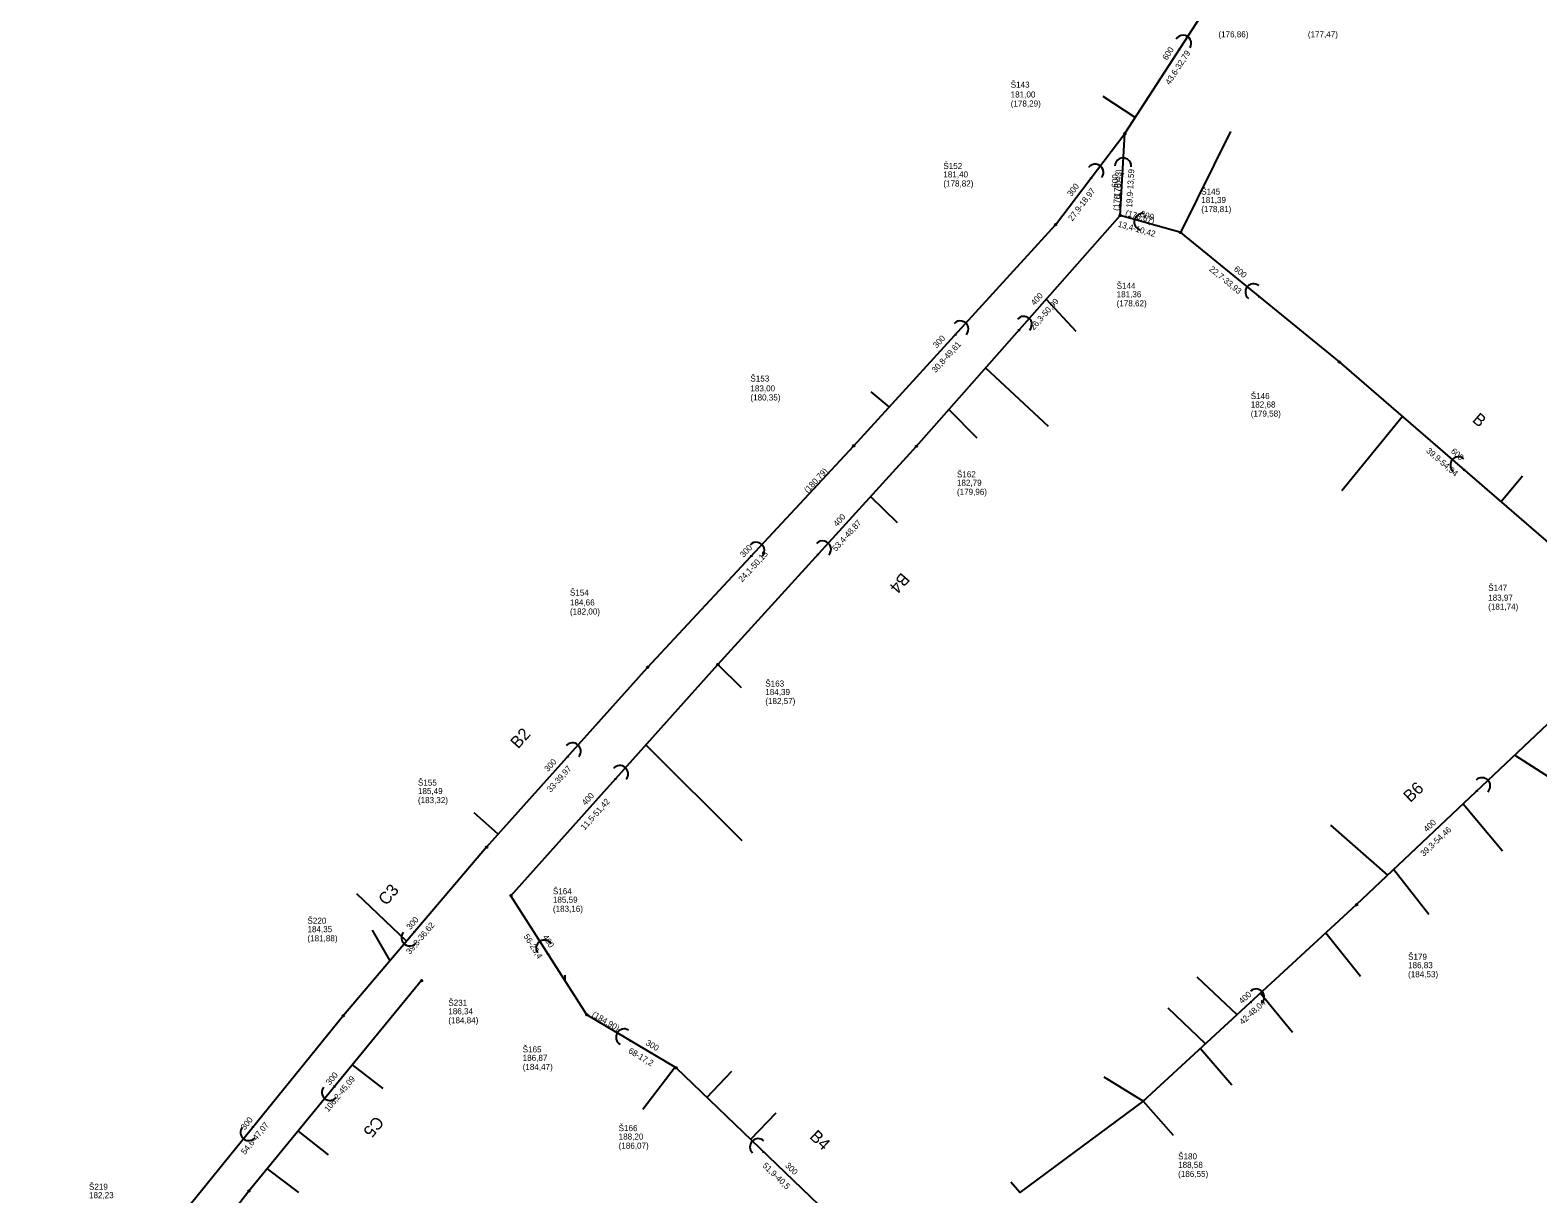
# Model space of a CAD drawing. Extents: x -548529 to -543591, y -1201432 to -1192608.
# Drawn here: x -547313.2 to -547063.4, y -1195608.4 to -1195415.6 of the extents above; entities that cross this region are included whole.
import ezdxf

# ---------------------------------------------------------------- set-up
doc = ezdxf.new("R2010")
doc.units = 0
for name, color, linetype in [('C3D_Bod-Značky', 7, 'Continuous'), ('C3D_Koridor', 7, 'Continuous'), ('C3D_Křižovatka', 7, 'Continuous'), ('C3D_Netisknutelná', 7, 'Continuous'), ('C3D_PP-zobrazeni v PR', 7, 'Continuous'), ('C3D_PR-Popisek', 7, 'Continuous'), ('C3D_SPR-Popisek', 7, 'Continuous'), ('C3D_Tlakove_potrubi_Popis', 7, 'Continuous'), ('C3D_ZPR-Formaty', 7, 'Continuous')]:
    doc.layers.add(name, color=color, linetype=linetype)

# ---------------------------------------------------------------- blocks, each defined once
blk = doc.blocks.new('100')
at = {"layer": 'Defpoints'}
blk.add_circle((0, 0), 0.127, dxfattribs=at)
blk = doc.blocks.new('91')
at = {"layer": 'Defpoints'}
blk.add_lwpolyline([(0.08, 0.14), (0.19, 0), (0.08, -0.14)], dxfattribs=at)
blk.add_arc((1.37, 0), 1.37, 270, 90, dxfattribs=at)

msp = doc.modelspace()

# ---------------------------------------------------------------- linework, layer by layer
at = {"layer": 'C3D_Bod-Značky'}
for points in [[(-547131.79, -1195432.77), (-547113.989, -1195405.234)], [(-547143.271, -1195447.871), (-547131.79, -1195432.77)], [(-547132.58, -1195446.34), (-547131.79, -1195432.77)], [(-547176.727, -1195484.502), (-547143.271, -1195447.871)], [(-547166.33, -1195484.56), (-547132.58, -1195446.34)], [(-547122.55, -1195449.16), (-547132.58, -1195446.34)], [(-547096.26, -1195470.61), (-547122.55, -1195449.16)], [(-547054.66, -1195506.502), (-547096.26, -1195470.61)], [(-547210.875, -1195521.197), (-547176.727, -1195484.502)], [(-547199.21, -1195520.71), (-547166.33, -1195484.56)], [(-547233.52, -1195559.01), (-547199.21, -1195520.71)], [(-547237.551, -1195550.965), (-547210.875, -1195521.197)], [(-547093.408, -1195560.488), (-547053.816, -1195523.086)], [(-547237.551, -1195550.965), (-547261.272, -1195578.867)], [(-547220.936, -1195578.736), (-547233.52, -1195559.01)], [(-547128.742, -1195593.037), (-547093.408, -1195560.488)], [(-547248.319, -1195573.072), (-547276.928, -1195607.929)], [(-547261.272, -1195578.867), (-547290.91, -1195615.433)], [(-547206.156, -1195587.526), (-547220.936, -1195578.736)], [(-547176.934, -1195615.567), (-547206.156, -1195587.526)], [(-547276.928, -1195607.929), (-547313.169, -1195654.962)]]:
    msp.add_lwpolyline(points, dxfattribs=at)
at = {"layer": 'C3D_Koridor'}
for points in [[(-547130.085, -1195430.133), (-547135.399, -1195426.642)], [(-547122.55, -1195449.16), (-547114.266, -1195432.435)], [(-547144.825, -1195460.207), (-547139.897, -1195465.528)], [(-547154.868, -1195471.58), (-547144.509, -1195481.216)], [(-547170.84, -1195478.056), (-547173.82, -1195475.538)], [(-547160.955, -1195478.473), (-547156.335, -1195483.183)], [(-547085.805, -1195479.631), (-547095.873, -1195491.943)], [(-547069.46, -1195493.733), (-547065.908, -1195489.486)], [(-547173.915, -1195492.9), (-547169.546, -1195497.207)], [(-547199.21, -1195520.71), (-547195.388, -1195524.535)], [(-547211.139, -1195534.027), (-547195.246, -1195549.866)], [(-547067.195, -1195535.74), (-547057.976, -1195541.659)], [(-547235.636, -1195548.828), (-547239.621, -1195545.288)], [(-547075.735, -1195543.793), (-547069.215, -1195551.573)], [(-547088.235, -1195555.582), (-547097.7, -1195547.337)], [(-547087.226, -1195554.648), (-547081.424, -1195562.086)], [(-547250.801, -1195566.568), (-547259.041, -1195558.69)], [(-547253.55, -1195569.784), (-547256.443, -1195564.732)], [(-547098.495, -1195565.174), (-547092.762, -1195572.313)], [(-547224.522, -1195573.114), (-547224.514, -1195572.189)], [(-547113.207, -1195578.744), (-547119.818, -1195572.495)], [(-547109.351, -1195575.175), (-547104.003, -1195581.606)], [(-547118.452, -1195583.559), (-547124.652, -1195577.614)], [(-547119.254, -1195584.297), (-547114.097, -1195590.323)], [(-547259.793, -1195587.051), (-547254.762, -1195590.956)], [(-547206.302, -1195587.439), (-547211.686, -1195594.41)], [(-547201.048, -1195592.428), (-547196.933, -1195588.088)], [(-547128.742, -1195593.037), (-547135.214, -1195589.056)], [(-547128.742, -1195593.037), (-547149.176, -1195608.175), (-547150.713, -1195606.436)], [(-547128.742, -1195593.037), (-547123.8, -1195598.654)], [(-547193.796, -1195599.386), (-547189.589, -1195595.003)], [(-547268.787, -1195598.01), (-547263.77, -1195601.94)], [(-547273.913, -1195604.255), (-547268.737, -1195608.146)]]:
    msp.add_lwpolyline(points, dxfattribs=at)

# ---------------------------------------------------------------- block references
at = {"layer": 'C3D_PP-zobrazeni v PR'}
for p, xscale, yscale, rotation in [((-547131.79, -1195432.77), 1.000000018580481, 1.000000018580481, -125.00000023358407), ((-547143.271, -1195447.871), 1.000000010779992, 1.0000000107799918, -128.99999891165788), ((-547132.58, -1195446.34), 1.000000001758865, 1.000000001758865, 125.99999933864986), ((-547122.55, -1195449.16), 1.0106518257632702, 1.0106518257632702, 151.83788426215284), ((-547096.26, -1195470.61), 1.0000000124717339, 1.0000000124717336, 139.99999868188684), ((-547176.727, -1195484.502), 1.0000000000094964, 1.0000000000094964, -132.0000013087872), ((-547166.33, -1195484.56), 1.0000000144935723, 1.0000000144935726, -130.99999910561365), ((-547199.21, -1195520.71), 1.0000000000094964, 1.0000000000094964, -132.0000013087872), ((-547210.875, -1195521.197), 1.0000000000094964, 1.0000000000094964, -132.0000013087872), ((-547237.551, -1195550.965), 1.0000000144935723, 1.0000000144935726, -130.99999910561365), ((-547233.52, -1195559.01), 1.0000000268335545, 1.0000000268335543, 86.00000028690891), ((-547093.408, -1195560.488), 1.0000000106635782, 1.0000000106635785, -135.99999834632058), ((-547248.319, -1195573.072), 1.000000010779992, 1.0000000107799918, 51.00000108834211), ((-547261.272, -1195578.867), 1.000000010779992, 1.0000000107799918, -128.99999891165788), ((-547220.936, -1195578.736), 1.0000000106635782, 1.0000000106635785, 135.99999834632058), ((-547206.156, -1195587.526), 0.9999999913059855, 0.9999999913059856, 142.99999806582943), ((-547128.742, -1195593.037), 1.00000000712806, 1.00000000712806, -136.99999943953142), ((-547276.928, -1195607.929), 1.000000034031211, 1.0000000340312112, -128.00000040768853)]:
    msp.add_blockref('100', p, dxfattribs=dict(at, xscale=xscale, yscale=yscale, rotation=rotation))
at = {"layer": 'C3D_SPR-Popisek'}
for p, xscale, yscale, rotation in [((-547122.89, -1195419.002), 0.9999999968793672, 0.9999999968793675, 57.99999972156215), ((-547137.53, -1195440.32), 0.9999999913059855, 0.9999999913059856, 52.999998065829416), ((-547132.185, -1195439.555), 0.9999999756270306, 0.9999999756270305, 86.99999998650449), ((-547127.565, -1195447.75), 0.999999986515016, 0.9999999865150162, 164.99999987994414), ((-547109.405, -1195459.885), 1.000000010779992, 1.0000000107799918, 141.00000108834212), ((-547159.999, -1195466.186), 1.0000000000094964, 1.0000000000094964, 47.99999869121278), ((-547149.455, -1195465.45), 1.0000000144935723, 1.0000000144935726, 49.00000089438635), ((-547075.46, -1195488.556), 1.0000000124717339, 1.0000000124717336, 139.99999868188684), ((-547193.801, -1195502.85), 1.0000000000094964, 1.0000000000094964, 47.99999869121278), ((-547182.77, -1195502.635), 1.0000000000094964, 1.0000000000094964, 47.99999869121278), ((-547224.213, -1195536.081), 1.0000000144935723, 1.0000000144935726, 49.00000089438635), ((-547216.365, -1195539.86), 1.0000000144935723, 1.0000000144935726, 49.00000089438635), ((-547073.612, -1195541.787), 1.0000000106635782, 1.0000000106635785, 44.00000165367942), ((-547249.411, -1195564.916), 1.0000000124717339, 1.0000000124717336, -130.0000013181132), ((-547227.228, -1195568.873), 0.9999999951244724, 0.9999999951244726, 123.00000127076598), ((-547111.075, -1195576.762), 1.00000000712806, 1.00000000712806, 43.0000005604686), ((-547213.546, -1195583.131), 0.9999999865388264, 0.9999999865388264, 149.99999955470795), ((-547262.624, -1195590.5), 1.000000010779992, 1.0000000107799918, -128.99999891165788), ((-547276.091, -1195597.15), 1.000000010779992, 1.0000000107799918, -128.99999891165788), ((-547191.545, -1195601.547), 1.00000000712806, 1.00000000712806, 136.99999943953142)]:
    msp.add_blockref('91', p, dxfattribs=dict(at, xscale=xscale, yscale=yscale, rotation=rotation))

# ---------------------------------------------------------------- texts
at = {"layer": 'C3D_Křižovatka'}
for s, p in [('Š143', (-547150.71, -1195425.17)), ('Š152', (-547161.871, -1195438.641)), ('Š145', (-547119.14, -1195442.88)), ('Š144', (-547133.16, -1195458.49)), ('Š153', (-547193.837, -1195473.852)), ('Š146', (-547110.94, -1195476.75)), ('Š162', (-547159.62, -1195489.71)), ('Š154', (-547223.735, -1195509.307)), ('Š147', (-547071.6, -1195508.512)), ('Š163', (-547191.37, -1195524.37)), ('Š155', (-547248.921, -1195540.775)), ('Š164', (-547226.56, -1195558.77)), ('Š220', (-547267.222, -1195563.657)), ('Š179', (-547084.878, -1195569.618)), ('Š231', (-547243.889, -1195577.242)), ('Š165', (-547231.566, -1195584.966)), ('Š166', (-547215.666, -1195598.006)), ('Š180', (-547122.972, -1195602.687)), ('Š219', (-547303.42, -1195607.713))]:
    msp.add_text(s, height=1, dxfattribs=at).set_placement(p)
at = {"layer": 'C3D_Netisknutelná'}
for s, rotation, p in [('B', 319.21, (-547074.372, -1195480.379)), ('B4', 228.99, (-547168.786, -1195505.371)), ('B2', 48.14, (-547232.319, -1195534.787)), ('B6', 43.37, (-547084.512, -1195543.672)), ('C3', 49.63, (-547254.16, -1195560.761)), ('C5', 230.42, (-547255.929, -1195595.357)), ('B4', 316.18, (-547184.161, -1195599.069))]:
    msp.add_text(s, height=2, rotation=rotation, dxfattribs=at).set_placement(p)
at = {"layer": 'C3D_PR-Popisek'}
for s, rotation, p in [('600', 57.12, (-547124.833, -1195420.72)), ('600', 86.67, (-547133.016, -1195441.77)), ('300', 52.75, (-547140.664, -1195443.286)), ('500', 344.3, (-547129.303, -1195446.534)), ('600', 320.79, (-547113.829, -1195455.367)), ('400', 48.55, (-547146.756, -1195461.341)), ('300', 47.59, (-547162.971, -1195468.399)), ('600', 319.21, (-547077.879, -1195485.54)), ('400', 47.71, (-547179.473, -1195497.966)), ('300', 47.06, (-547194.964, -1195503.068)), ('300', 48.14, (-547227.359, -1195538.549)), ('400', 48.15, (-547221.14, -1195544.147)), ('400', 43.37, (-547081.761, -1195548.529)), ('300', 49.63, (-547250.167, -1195564.729)), ('400', 302.54, (-547228.32, -1195565.861)), ('400', 42.65, (-547112.376, -1195577.007)), ('300', 329.26, (-547211.287, -1195583.657)), ('300', 50.62, (-547263.51, -1195590.471)), ('300', 50.97, (-547277.603, -1195597.907)), ('300', 316.18, (-547188.17, -1195603.812))]:
    msp.add_text(s, height=1, rotation=rotation, dxfattribs=at).set_placement(p)
at = {"layer": 'C3D_Tlakove_potrubi_Popis'}
for s, p in [('(176,86)', (-547116.299, -1195416.834)), ('(177,47)', (-547101.478, -1195416.827)), ('181,00 ', (-547150.71, -1195426.8)), ('(178,29)', (-547150.71, -1195428.3)), ('(178,82)', (-547161.871, -1195441.541)), ('181,40 ', (-547161.871, -1195440.041)), ('181,39 ', (-547119.14, -1195444.28)), ('(178,81)', (-547119.14, -1195445.78)), ('(178,62)', (-547133.16, -1195461.39)), ('181,36 ', (-547133.16, -1195459.89)), ('(180,35)', (-547193.837, -1195476.982)), ('183,00 ', (-547193.837, -1195475.482)), ('182,68 ', (-547110.94, -1195478.15)), ('(179,58)', (-547110.94, -1195479.65)), ('182,79 ', (-547159.62, -1195491.11)), ('(179,96)', (-547159.62, -1195492.61)), ('184,66 ', (-547223.735, -1195510.937)), ('(181,74)', (-547071.6, -1195511.642)), ('183,97 ', (-547071.6, -1195510.142)), ('(182,00)', (-547223.735, -1195512.437)), ('184,39 ', (-547191.37, -1195525.77)), ('(182,57)', (-547191.37, -1195527.27)), ('(183,32)', (-547248.921, -1195543.675)), ('185,49 ', (-547248.921, -1195542.175)), ('(183,16)', (-547226.56, -1195561.67)), ('185,59 ', (-547226.56, -1195560.17)), ('(181,88)', (-547267.222, -1195566.557)), ('184,35 ', (-547267.222, -1195565.057)), ('186,83 ', (-547084.878, -1195571.018)), ('(184,53)', (-547084.878, -1195572.518)), ('186,34 ', (-547243.889, -1195578.642)), ('(184,84)', (-547243.889, -1195580.142)), ('186,87 ', (-547231.566, -1195586.366)), ('(184,47)', (-547231.566, -1195587.866)), ('188,20 ', (-547215.666, -1195599.406)), ('(186,07)', (-547215.666, -1195600.906)), ('188,58 ', (-547122.972, -1195604.087)), ('(186,55)', (-547122.972, -1195605.587)), ('182,23 ', (-547303.42, -1195609.113))]:
    msp.add_text(s, height=1, dxfattribs=at).set_placement(p)
at = {"layer": 'C3D_ZPR-Formaty'}
for s, rotation, p in [('43,6-32,79', 57.12, (-547124.357, -1195424.776)), ('  (178,70)   ', 86.67, (-547132.78, -1195446.328)), ('  (178,43)   ', 86.67, (-547132.669, -1195444.439)), ('19,9-13,59', 86.67, (-547130.601, -1195445.066)), ('27,9-18,97', 52.75, (-547140.497, -1195447.36)), ('  (178,67)   ', 344.3, (-547132.526, -1195446.147)), ('13,4-10,42', 344.3, (-547133.044, -1195448.18)), ('22,7-33,93', 320.79, (-547117.914, -1195455.39)), ('26,3-50,99', 48.55, (-547146.901, -1195465.419)), ('30,8-49,61', 47.59, (-547163.172, -1195472.479)), ('39,9-54,94', 319.21, (-547081.969, -1195485.452)), ('  (180,79)   ', 47.06, (-547184.844, -1195492.931)), ('53,4-48,87', 47.71, (-547179.667, -1195502.048)), ('24,1-50,13', 47.06, (-547195.205, -1195507.148)), ('33-39,97', 48.14, (-547226.928, -1195541.959)), ('11,5-51,42', 48.15, (-547221.308, -1195548.228)), ('39,3-54,46', 43.37, (-547082.269, -1195552.58)), ('39,3-36,62', 49.63, (-547250.23, -1195568.806)), ('56-23,4', 302.54, (-547231.478, -1195565.747)), ('  (184,90)   ', 329.26, (-547220.834, -1195578.564)), ('42-48,04', 42.65, (-547112.273, -1195580.441)), ('68-17,2', 329.26, (-547214.17, -1195584.97)), ('106,2-45,09', 50.62, (-547263.782, -1195594.901)), ('54,6-47,07', 50.97, (-547277.57, -1195601.985)), ('51,9-40,5', 316.18, (-547191.917, -1195603.823))]:
    msp.add_text(s, height=1, rotation=rotation, dxfattribs=at).set_placement(p)

doc.saveas('drawing.dxf')
